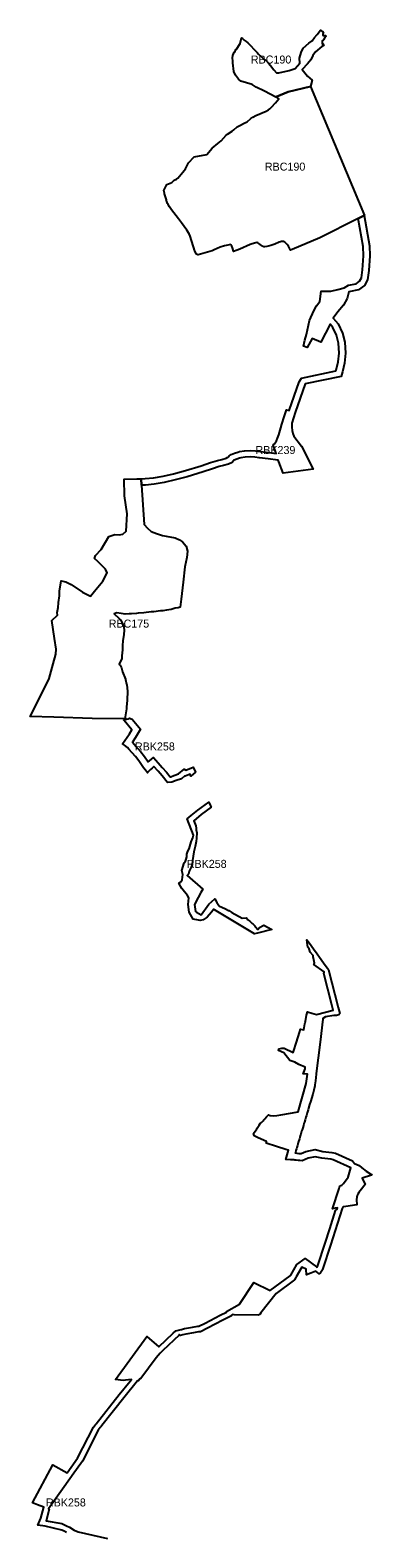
# Model space of a CAD drawing. Extents: x -559776 to -467147, y -1204122 to -1132159.
# Drawn here: x -525080 to -522945, y -1154789 to -1145407 of the extents above; entities that cross this region are included whole.
import ezdxf

# ---------------------------------------------------------------- set-up
doc = ezdxf.new("R2010")
doc.units = 0
doc.layers.add('regionalni_biocentrum_biokoridor', color=7, linetype='Continuous')

msp = doc.modelspace()

# ---------------------------------------------------------------- linework, layer by layer
at = {"layer": 'regionalni_biocentrum_biokoridor'}
for points in [[(-523328.59, -1145759.88), (-523468.67, -1145793.27), (-523542.77, -1145824.46), (-523545.77, -1145825.76), (-523615.41, -1145789.03), (-523667.45, -1145764.48), (-523693.27, -1145747.46), (-523763.57, -1145725.75), (-523777.48, -1145714.77), (-523796.61, -1145689.31), (-523807.7, -1145667.19), (-523813.88, -1145612.28), (-523814.22, -1145601.9), (-523815.48, -1145581.37), (-523813.04, -1145566.01), (-523804.95, -1145544.98), (-523801.67, -1145545.79), (-523794.39, -1145528.05), (-523790.57, -1145526.9), (-523768.76, -1145491.91), (-523759.9, -1145456.56), (-523754.01, -1145461.15), (-523742.67, -1145469.98), (-523731.15, -1145478.96), (-523720.44, -1145487.29), (-523713.2, -1145492.93), (-523709.93, -1145496.71), (-523701.08, -1145506.91), (-523683.05, -1145527.68), (-523672.48, -1145537.49), (-523666.5, -1145543.03), (-523662.57, -1145547.35), (-523653.56, -1145557.25), (-523643.62, -1145568.17), (-523643.15, -1145568.68), (-523632.99, -1145577.14), (-523621.63, -1145586.6), (-523611.12, -1145595.35), (-523600.24, -1145604.4), (-523598.48, -1145605.86), (-523590.58, -1145614.97), (-523579.19, -1145628.08), (-523558.38, -1145656.57), (-523540.6, -1145673.73), (-523527.41, -1145673.73), (-523461.42, -1145660.6), (-523424.36, -1145648.48), (-523395.43, -1145614.65), (-523398.27, -1145583.54), (-523387.82, -1145547.98), (-523375.43, -1145520.7), (-523338.07, -1145488.38), (-523317.77, -1145474.54), (-523304.56, -1145454.75), (-523287.31, -1145435.76), (-523267.06, -1145407.28), (-523256.85, -1145416.46), (-523251.78, -1145417.17), (-523247.21, -1145423.64), (-523252.49, -1145431.72), (-523251.98, -1145438.38), (-523247.51, -1145441.92), (-523235.53, -1145441.41), (-523231.47, -1145445.45), (-523239.59, -1145454.04), (-523247.41, -1145467.68), (-523256.65, -1145474.75), (-523256.35, -1145485.86), (-523254.82, -1145493.43), (-523248.73, -1145493.43), (-523245.69, -1145500.61), (-523246.7, -1145503.84), (-523258.38, -1145509.7), (-523298.48, -1145542.63), (-523314.72, -1145567.17), (-523326.29, -1145592.73), (-523347.82, -1145618.18), (-523380.71, -1145653.54), (-523346.6, -1145696.46), (-523317.28, -1145721.27)], [(-522992.95, -1146566.65), (-523030.28, -1146585.27), (-523269.51, -1146704.64), (-523442.49, -1146778.16), (-523452.8, -1146782.54), (-523466.08, -1146758.05), (-523474.04, -1146747.08), (-523488.03, -1146733.36), (-523497.91, -1146728.14), (-523504.09, -1146727.73), (-523513, -1146728.42), (-523515.75, -1146730.06), (-523523.84, -1146732.12), (-523551.69, -1146744.33), (-523576.39, -1146753.66), (-523601.63, -1146760.39), (-523612.88, -1146761.62), (-523619.47, -1146760.93), (-523630.44, -1146756.96), (-523635.52, -1146753.8), (-523650.75, -1146741.04), (-523657.34, -1146737.2), (-523664.74, -1146735.42), (-523670.78, -1146736.1), (-523693.56, -1146742.41), (-523704.53, -1146746.39), (-523769.84, -1146775.2), (-523786.28, -1146783.25), (-523809.62, -1146790.84), (-523809.97, -1146789.34), (-523815.13, -1146767.36), (-523819.69, -1146756.52), (-523825.77, -1146748.54), (-523829.13, -1146746.5), (-523845.3, -1146751.21), (-523865.35, -1146755.53), (-523892.08, -1146764.3), (-523929.45, -1146780.09), (-523942.48, -1146785.88), (-523972.89, -1146794.24), (-524031.16, -1146811.22), (-524032.66, -1146810.55), (-524041.24, -1146806.75), (-524048.27, -1146792.49), (-524055.49, -1146775.19), (-524056.17, -1146774.65), (-524061.93, -1146755.04), (-524080.73, -1146695.49), (-524087.18, -1146679.85), (-524101.31, -1146657.62), (-524135.06, -1146610.7), (-524153.53, -1146586.43), (-524168.26, -1146567.07), (-524197.76, -1146529.34), (-524209.69, -1146512.33), (-524218.2, -1146497.93), (-524222.32, -1146489.83), (-524226.57, -1146478.44), (-524229.39, -1146469.62), (-524227.27, -1146468.88), (-524240.45, -1146431.11), (-524241.49, -1146425.98), (-524244.67, -1146410.3), (-524225.11, -1146371.91), (-524195.5, -1146360.39), (-524179.33, -1146345.85), (-524165.85, -1146339.54), (-524156.42, -1146332.59), (-524126.78, -1146295.94), (-524110.34, -1146274.91), (-524090.06, -1146236.29), (-524055.32, -1146200.17), (-523976.43, -1146183.94), (-523942.62, -1146145.31), (-523908.09, -1146116.91), (-523887.2, -1146098.39), (-523854.77, -1146064.28), (-523847.53, -1146058.02), (-523817.45, -1146038.39), (-523807.43, -1146030.73), (-523786.83, -1146012.91), (-523774.29, -1146004.98), (-523738.93, -1145987.85), (-523725.01, -1145979.64), (-523701.62, -1145960.7), (-523688.53, -1145951.65), (-523669.32, -1145941.91), (-523605.28, -1145913.78), (-523590.1, -1145905.01), (-523581.89, -1145899.03), (-523571.59, -1145889.84), (-523546.8, -1145862.69), (-523526.82, -1145837.59), (-523525.63, -1145836.09), (-523542.77, -1145824.46), (-523468.67, -1145793.27), (-523328.59, -1145759.88), (-522991.63, -1146565.99)], [(-524384.36, -1148249.93), (-524387.2, -1148209.97), (-524360.86, -1148209.51), (-524310.26, -1148203.96), (-524249.87, -1148193.85), (-524184.46, -1148178.87), (-524109.46, -1148159.43), (-524010.79, -1148128.75), (-523953.91, -1148109.23), (-523910.07, -1148096), (-523881.6, -1148089.3), (-523855.21, -1148081.54), (-523844.16, -1148076.32), (-523843.28, -1148075.03), (-523837.47, -1148066.48), (-523823.87, -1148058.7), (-523803.1, -1148050.06), (-523783.55, -1148043.69), (-523771.2, -1148040.84), (-523740.54, -1148035.82), (-523704.99, -1148033.9), (-523673, -1148035.53), (-523642.94, -1148039.71), (-523641.55, -1148039.9), (-523588.54, -1148046.6), (-523588.34, -1148046.62), (-523586.84, -1148046.83), (-523544, -1148052.69), (-523562.36, -1147997.98), (-523553.74, -1147992.07), (-523541.36, -1147973.6), (-523534.7, -1147957.22), (-523527.12, -1147935.5), (-523513.12, -1147891.4), (-523506.7, -1147869.02), (-523492.7, -1147824.16), (-523478.7, -1147779.3), (-523462.51, -1147784.13), (-523400.32, -1147604.66), (-523384.75, -1147581.52), (-523169.63, -1147536.82), (-523168.02, -1147531.27), (-523155.93, -1147480.28), (-523149.35, -1147425.09), (-523153.27, -1147362.43), (-523166.15, -1147313.53), (-523189.1, -1147265.14), (-523206.66, -1147245.13), (-523265.17, -1147356.89), (-523319.05, -1147334.98), (-523348.92, -1147390.4), (-523373.08, -1147381.76), (-523364.97, -1147343.97), (-523352.7, -1147309.95), (-523334.45, -1147221.4), (-523307.51, -1147160.71), (-523291.18, -1147129.37), (-523269.94, -1147103.66), (-523262.99, -1147037.75), (-523202.43, -1147037.39), (-523158.09, -1147027.7), (-523119.3, -1147016.63), (-523091.75, -1147000.98), (-523044.3, -1146992.34), (-523022.55, -1146976.82), (-523011.03, -1146954.93), (-523004.31, -1146905.7), (-522997.18, -1146817.87), (-522999.43, -1146759.75), (-523030.28, -1146585.27), (-522992.95, -1146566.65), (-522959.56, -1146755.48), (-522957.11, -1146818.71), (-522964.53, -1146910.03), (-522972.35, -1146967.32), (-522991.59, -1147003.87), (-523028.03, -1147029.86), (-523089.24, -1147042.19), (-523089.18, -1147043.08), (-523098.8, -1147084.61), (-523122.9, -1147125.18), (-523157.66, -1147167.66), (-523186.51, -1147207.46), (-523155.35, -1147242.95), (-523128.42, -1147299.75), (-523113.59, -1147356.03), (-523109.2, -1147426.22), (-523116.48, -1147487.29), (-523129.33, -1147541.48), (-523137.93, -1147571.09), (-523362.52, -1147617.76), (-523424.14, -1147795.57), (-523446.06, -1147862.43), (-523445.99, -1147888.99), (-523443.71, -1147908.35), (-523439.28, -1147927.72), (-523433.19, -1147944.04), (-523385.73, -1148005.81), (-523311.46, -1148149.56), (-523499.46, -1148174.39), (-523526.76, -1148104.05), (-523529.84, -1148094.88), (-523531.97, -1148094.71), (-523592.25, -1148086.46), (-523593.68, -1148086.27), (-523646.71, -1148079.57), (-523646.98, -1148079.53), (-523648.47, -1148079.33), (-523676.78, -1148075.39), (-523704.93, -1148073.96), (-523736.22, -1148075.65), (-523763.47, -1148080.11), (-523772.84, -1148082.27), (-523789.2, -1148087.6), (-523806.18, -1148094.67), (-523809.59, -1148096.61), (-523810.19, -1148097.51), (-523817.2, -1148107.83), (-523840.95, -1148119.04), (-523871.37, -1148127.98), (-523899.7, -1148134.65), (-523941.63, -1148147.31), (-523998.35, -1148166.78), (-524098.5, -1148197.91), (-524174.97, -1148217.74), (-524242.1, -1148233.11), (-524304.78, -1148243.6), (-524358.32, -1148249.47)], [(-524384.36, -1148249.93), (-524366.88, -1148496.4), (-524346.87, -1148519.61), (-524323.9, -1148538.81), (-524291.41, -1148552.58), (-524252.45, -1148564.25), (-524230.46, -1148567.93), (-524173.78, -1148579.79), (-524146.15, -1148591.09), (-524127.26, -1148603.24), (-524105.83, -1148631.5), (-524097.64, -1148663.09), (-524101.88, -1148702.7), (-524113.16, -1148759.77), (-524123.88, -1148857.03), (-524136.61, -1148962.35), (-524142.42, -1149012.96), (-524156.26, -1149015.45), (-524172.23, -1149018.02), (-524173.23, -1149018.28), (-524187.43, -1149022.01), (-524199.6, -1149026), (-524227.53, -1149031.42), (-524251.68, -1149034.3), (-524264.85, -1149035.26), (-524307.55, -1149041.08), (-524322.14, -1149041.98), (-524322.95, -1149042.03), (-524369.71, -1149047.64), (-524405.64, -1149050.21), (-524415.52, -1149051.54), (-524446.68, -1149053.92), (-524449.17, -1149054.11), (-524450.55, -1149054.13), (-524461.34, -1149054.3), (-524486.62, -1149055.72), (-524511.07, -1149051.13), (-524538, -1149048.71), (-524553.96, -1149054.81), (-524525.62, -1149081.95), (-524514.99, -1149092.38), (-524506.29, -1149105.27), (-524500.34, -1149118.02), (-524494.39, -1149138.01), (-524492.47, -1149156.29), (-524493.75, -1149183.07), (-524500.55, -1149221.76), (-524503.95, -1149251.1), (-524502.87, -1149276.81), (-524503.22, -1149279.81), (-524506.08, -1149316.16), (-524508.06, -1149332.02), (-524514.86, -1149350.99), (-524523.07, -1149366.28), (-524519.57, -1149371.88), (-524517.4, -1149375.34), (-524510.04, -1149392.05), (-524502.12, -1149415.56), (-524484.33, -1149462.18), (-524483.76, -1149463.68), (-524476.96, -1149494.29), (-524476.67, -1149496.97), (-524472.28, -1149536.81), (-524473.77, -1149592.5), (-524477.6, -1149636.72), (-524478.9, -1149646.95), (-524485.25, -1149696.67), (-524483.35, -1149710.27), (-524691.47, -1149706.92), (-524932.69, -1149699.88), (-525080.41, -1149695.23), (-524988.64, -1149513.2), (-524960.53, -1149457.55), (-524935, -1149365.78), (-524918.32, -1149306.51), (-524917.56, -1149274.2), (-524926.95, -1149208.56), (-524944.02, -1149094.74), (-524909.04, -1149061.6), (-524910.3, -1149045.45), (-524904.13, -1149014.17), (-524903.47, -1148985.33), (-524903.27, -1148984.06), (-524896.51, -1148941.54), (-524897.16, -1148912.13), (-524885.39, -1148847.75), (-524857.29, -1148854.94), (-524823.94, -1148870.51), (-524752.05, -1148917.96), (-524703.06, -1148944.4), (-524676.85, -1148912.03), (-524626.72, -1148850.11), (-524598.78, -1148798.81), (-524608.77, -1148775.04), (-524614.84, -1148769.05), (-524657.84, -1148726.61), (-524678.33, -1148707.54), (-524671.48, -1148690.01), (-524636.19, -1148652.17), (-524588.31, -1148570.21), (-524551.77, -1148557.6), (-524524.04, -1148560.12), (-524500.22, -1148555.58), (-524479.72, -1148536.72), (-524473.36, -1148428.6), (-524491.08, -1148316.9), (-524492.33, -1148213.37), (-524413.53, -1148210.44), (-524387.2, -1148209.97)], [(-524364.97, -1149945.85), (-524342.06, -1149978.76), (-524336, -1149973.44), (-524334.02, -1149972.11), (-524309.74, -1149950.99), (-524280.2, -1149984.94), (-524254.67, -1150014.3), (-524228.9, -1150043.63), (-524205.34, -1150071.81), (-524202.06, -1150071.47), (-524181.76, -1150064.13), (-524152.65, -1150053.61), (-524118.61, -1150023.54), (-524108.08, -1150029.64), (-524061.87, -1150011.58), (-524047.91, -1150043.68), (-524075.86, -1150067.15), (-524080.52, -1150056.45), (-524111.03, -1150068.37), (-524114.34, -1150066.46), (-524134.48, -1150084.26), (-524166.91, -1150095.99), (-524194.19, -1150105.85), (-524219.25, -1150108.44), (-524223.51, -1150104.64), (-524255.48, -1150066.41), (-524281.02, -1150037.33), (-524306.61, -1150007.91), (-524308.5, -1150009.18), (-524318.5, -1150017.95), (-524328.49, -1150026.73), (-524342.8, -1150040.73), (-524347.38, -1150046.59), (-524359.18, -1150031.29), (-524370.98, -1150015.98), (-524401.24, -1149972.51), (-524422.58, -1149944.98), (-524442.52, -1149921.66), (-524462.46, -1149898.33), (-524472.06, -1149888.46), (-524490.35, -1149874.07), (-524502.75, -1149865.19), (-524459.38, -1149802.59), (-524444.91, -1149777.9), (-524493.33, -1149719.62), (-524495.53, -1149717.16), (-524494.71, -1149716.98), (-524493.03, -1149716.42), (-524467.23, -1149708.89), (-524459.72, -1149706.14), (-524441.52, -1149711.55), (-524390.14, -1149773.41), (-524421.42, -1149826.81), (-524441.32, -1149855.53), (-524429.2, -1149867.99), (-524408.31, -1149892.42), (-524387.68, -1149916.56)], [(-524039.95, -1150916.85), (-524010.61, -1150934.3), (-523964.34, -1150867.19), (-523927.03, -1150833.79), (-523913.6, -1150856.3), (-523908.92, -1150864.17), (-523901.66, -1150876.36), (-523900.33, -1150877.64), (-523897.63, -1150880.96), (-523882.7, -1150887.14), (-523860.13, -1150896.48), (-523841.01, -1150906.16), (-523837.85, -1150907.1), (-523820.03, -1150918.74), (-523756.3, -1150954.41), (-523728.56, -1150953.28), (-523719.83, -1150965.3), (-523707.49, -1150974.56), (-523692.26, -1150987.64), (-523687.06, -1150993.11), (-523676.9, -1151003.78), (-523671.29, -1151009.68), (-523656.71, -1151025.02), (-523647.43, -1151013.05), (-523624.35, -1151001.21), (-523623.67, -1151000.86), (-523620.52, -1150999.68), (-523569.52, -1151026.57), (-523660.12, -1151047.84), (-523677.59, -1151051.94), (-523928.99, -1150902.12), (-523932.16, -1150898.6), (-523947.53, -1150917.06), (-523973.28, -1150947.79), (-523999.04, -1150965.25), (-524018.42, -1150968.89), (-524028.09, -1150967.34), (-524061.84, -1150960.76), (-524086.77, -1150917.54), (-524093.24, -1150869.89), (-524088.69, -1150828.02), (-524097.36, -1150814.35), (-524133.06, -1150770.32), (-524148.78, -1150741.23), (-524150.56, -1150735.96), (-524141.27, -1150729.33), (-524130.16, -1150715.7), (-524125.44, -1150683.01), (-524131.35, -1150656.27), (-524118.03, -1150609.21), (-524109.91, -1150599.2), (-524104.88, -1150586.61), (-524101.03, -1150572.23), (-524100.14, -1150554.54), (-524095.4, -1150536.01), (-524087.42, -1150522.44), (-524074.11, -1150478.48), (-524063.61, -1150453.66), (-524059.46, -1150436.57), (-524099.54, -1150335.38), (-524073.03, -1150313.3), (-524033.16, -1150280.09), (-523963.56, -1150229.51), (-523952.79, -1150254.02), (-523948.96, -1150262.17), (-524011.65, -1150307.72), (-524057.69, -1150346.07), (-524044.68, -1150378.98), (-524042.03, -1150393.67), (-524042.85, -1150400.81), (-524042.94, -1150402.61), (-524043.02, -1150404.07), (-524039.65, -1150422.9), (-524041.4, -1150454.35), (-524042.03, -1150475.28), (-524049.64, -1150507.19), (-524057.48, -1150541.57), (-524064.71, -1150595.61), (-524067.83, -1150618.76), (-524074.29, -1150636.48), (-524085.64, -1150661.79), (-524091.01, -1150680.91), (-524098.25, -1150688.28), (-524001.97, -1150773.9), (-524012.87, -1150794.96), (-524029.58, -1150826.3), (-524052.24, -1150869.06), (-524047.18, -1150913.87)]]:
    msp.add_lwpolyline(points, close=True, dxfattribs=at)
msp.add_lwpolyline([(-524853.55, -1154791.44), (-524866.54, -1154784.46), (-524882.36, -1154777.7), (-524985.49, -1154753.86), (-525030.75, -1154747.09), (-525011.97, -1154703.85), (-524993.35, -1154635.12), (-525034.76, -1154620.16), (-525065.28, -1154606.98), (-524939.01, -1154369.98), (-524848.55, -1154420.24), (-524783.61, -1154329.06), (-524684.22, -1154133.8), (-524672.35, -1154118.61), (-524667.75, -1154113.16), (-524522.71, -1153930.16), (-524455.15, -1153847.84), (-524445.71, -1153836.35), (-524484.31, -1153841.34), (-524498.21, -1153842.8), (-524547.57, -1153836.95), (-524351.57, -1153567.24), (-524276.96, -1153632.44), (-524186.14, -1153546.55), (-524170.71, -1153531.96), (-524136.65, -1153524.07), (-524134.86, -1153523.66), (-524115.08, -1153519.07), (-524065.79, -1153510.22), (-524032.8, -1153503.53), (-524025.18, -1153503.29), (-523986.98, -1153484.15), (-523892.42, -1153435.18), (-523853.73, -1153415.35), (-523853.13, -1153412.04), (-523772.42, -1153367.17), (-523681.61, -1153231.41), (-523579.66, -1153281.75), (-523455.05, -1153189.56), (-523451.99, -1153185.62), (-523452.56, -1153185.32), (-523413.48, -1153118.77), (-523361.89, -1153079.91), (-523291.79, -1153132.94), (-523286.37, -1153135.45), (-523284.2, -1153131.38), (-523281.99, -1153125.06), (-523236.99, -1152986.13), (-523207.9, -1152895.46), (-523171.77, -1152780.17), (-523162.88, -1152772.81), (-523160.46, -1152763.88), (-523175.28, -1152765.79), (-523191.81, -1152771.14), (-523150.5, -1152644.2), (-523144.56, -1152625.94), (-523138.99, -1152624.86), (-523132.47, -1152623.6), (-523123.51, -1152611.93), (-523092.98, -1152572.22), (-523076.02, -1152515.52), (-523187.63, -1152464.45), (-523201.92, -1152461.18), (-523258.75, -1152455.17), (-523299.85, -1152445.15), (-523344.3, -1152454.08), (-523379.91, -1152470.8), (-523394.98, -1152469.24), (-523405.49, -1152468.29), (-523417.84, -1152467.11), (-523426.94, -1152465.7), (-523431.9, -1152465.04), (-523452.73, -1152464.25), (-523483.39, -1152462.03), (-523466.85, -1152404.16), (-523481.76, -1152399.52), (-523540.39, -1152381.23), (-523605.71, -1152360.89), (-523602.64, -1152355.45), (-523603.9, -1152350.16), (-523654.78, -1152326.69), (-523680.58, -1152314.86), (-523681.18, -1152313.09), (-523683.07, -1152306.28), (-523684.6, -1152299.77), (-523679.88, -1152292.94), (-523673.17, -1152283.35), (-523668.66, -1152276.54), (-523664.77, -1152271.34), (-523661.46, -1152266.25), (-523657.59, -1152261.06), (-523653.58, -1152255.05), (-523649.22, -1152248.86), (-523642.24, -1152238.22), (-523635.67, -1152231.24), (-523625.34, -1152219.98), (-523620.37, -1152214.75), (-523613.81, -1152207.52), (-523603.91, -1152196.95), (-523597.97, -1152190.35), (-523591.56, -1152183.74), (-523581.02, -1152188.38), (-523562.06, -1152190.04), (-523538.36, -1152187.39), (-523514.45, -1152183.96), (-523405.65, -1152163.83), (-523356.17, -1151987.39), (-523348.43, -1151929.85), (-523363.25, -1151927.05), (-523375.06, -1151927.67), (-523363.01, -1151895.74), (-523361.18, -1151885.75), (-523402.02, -1151868.08), (-523426.67, -1151855.03), (-523457.83, -1151844.22), (-523496.22, -1151796.19), (-523528.96, -1151782.6), (-523526.92, -1151770.57), (-523508.19, -1151766.7), (-523492.3, -1151766.9), (-523436.5, -1151793.82), (-523435.01, -1151788.48), (-523415.89, -1151728.85), (-523397.16, -1151670.04), (-523390.62, -1151649.27), (-523370.66, -1151652.13), (-523363.13, -1151614.93), (-523361.65, -1151606.42), (-523360.52, -1151600.76), (-523358.91, -1151600.49), (-523353.03, -1151561.25), (-523348.26, -1151540.63), (-523320.07, -1151548.12), (-523291.32, -1151556.31), (-523187.5, -1151529.81), (-523195.69, -1151497.04), (-523246.21, -1151301.05), (-523243.76, -1151290.73), (-523244.02, -1151290.95), (-523308.81, -1151243.56), (-523303.86, -1151235.89), (-523309.9, -1151205.34), (-523310.3, -1151203.26), (-523311.18, -1151198.67), (-523313.07, -1151188.9), (-523330.27, -1151167.55), (-523337.21, -1151146.32), (-523345.29, -1151135.57), (-523349.92, -1151106.79), (-523350.59, -1151090.49), (-523334.5, -1151111.52), (-523309.94, -1151146.29), (-523286.75, -1151178.52), (-523272.63, -1151198.43), (-523247.49, -1151233.88), (-523218.8, -1151273.94), (-523217.97, -1151274.93), (-523216.07, -1151277.76), (-523155.6, -1151513.69), (-523144.76, -1151549.53), (-523150.68, -1151558.66), (-523165.72, -1151562.88), (-523182.96, -1151562.55), (-523235.73, -1151572.17), (-523251.46, -1151581.67), (-523250.56, -1151581.5), (-523250.98, -1151585), (-523268.28, -1151729.81), (-523293.14, -1151924.53), (-523293.36, -1151928.98), (-523298.26, -1151970.24), (-523301.25, -1151996.57), (-523301.81, -1152003.36), (-523308.7, -1152029.82), (-523314.69, -1152055.26), (-523328.36, -1152101.78), (-523334, -1152119.07), (-523341, -1152141.56), (-523344.21, -1152152.46), (-523349.57, -1152170.4), (-523354.43, -1152187.05), (-523357.8, -1152197.84), (-523362.75, -1152215.16), (-523366.78, -1152228.82), (-523369.75, -1152238.29), (-523373.21, -1152250.5), (-523377.58, -1152264.35), (-523381.44, -1152276.93), (-523384.16, -1152285.66), (-523386.14, -1152293.09), (-523389.51, -1152305.11), (-523392.56, -1152314.42), (-523395.86, -1152324.39), (-523398.08, -1152332.46), (-523400.22, -1152339.21), (-523403.52, -1152350.18), (-523405.16, -1152356.92), (-523407.64, -1152365.67), (-523410.6, -1152375.71), (-523414.31, -1152387.81), (-523416.45, -1152395.08), (-523419.91, -1152407.27), (-523423.12, -1152417.8), (-523424.14, -1152421.02), (-523414.41, -1152423.39), (-523401.44, -1152424.63), (-523390.75, -1152425.59), (-523387.51, -1152425.93), (-523358.14, -1152412.13), (-523298.93, -1152400.25), (-523251.22, -1152411.87), (-523194.69, -1152417.85), (-523173.46, -1152422.71), (-523066.85, -1152471.5), (-523053.39, -1152487.16), (-523024.52, -1152500.07), (-523009.07, -1152514.63), (-522981.51, -1152534.93), (-522951.14, -1152553.13), (-522944.82, -1152556.92), (-522946.76, -1152559.91), (-523005.67, -1152579.44), (-522986.41, -1152618.73), (-523018.97, -1152658.51), (-523027.56, -1152669.32), (-523033.1, -1152678.47), (-523036.98, -1152687.06), (-523039.48, -1152698.15), (-523041.14, -1152712.85), (-523040.16, -1152746.01), (-523108.77, -1152756.34), (-523125.17, -1152758.89), (-523127.28, -1152759.22), (-523131.3, -1152768.08), (-523174.54, -1152906.04), (-523203.68, -1152996.86), (-523250.96, -1153142.86), (-523254.36, -1153150.28), (-523253.49, -1153150.67), (-523265.28, -1153170.73), (-523274.04, -1153176.96), (-523296.1, -1153160.49), (-523325.78, -1153172.52), (-523353.02, -1153183.57), (-523355.6, -1153148.02), (-523382.18, -1153134.59), (-523418.3, -1153196.1), (-523420.31, -1153200.45), (-523428.48, -1153213.43), (-523543.23, -1153299.71), (-523638.26, -1153420.35), (-523645.21, -1153431.33), (-523655.45, -1153435.35), (-523805.01, -1153433.52), (-523815.07, -1153430.92), (-523821.65, -1153434.58), (-523822.38, -1153438.61), (-523876.39, -1153466.29), (-523971.09, -1153515.34), (-524016.38, -1153538.02), (-524028.73, -1153538.42), (-524059.22, -1153544.6), (-524108.04, -1153553.37), (-524126.96, -1153557.75), (-524140.59, -1153560.91), (-524149.81, -1153556.56), (-524149.43, -1153560.01), (-524250.49, -1153655.57), (-524267.39, -1153671.56), (-524291.78, -1153701.68), (-524388.84, -1153829.95), (-524393.26, -1153832.93), (-524394.06, -1153832.85), (-524403.97, -1153844.22), (-524408.27, -1153845.88), (-524495.47, -1153952.14), (-524631.14, -1154123.32), (-524632.98, -1154123.79), (-524636.87, -1154130.51), (-524642.59, -1154137.38), (-524654.57, -1154152.7), (-524753.6, -1154347.25), (-524817.77, -1154437.34), (-524820.98, -1154441.85), (-524964.93, -1154645.39), (-524960.32, -1154647.06), (-524979.88, -1154719.24), (-524881.77, -1154736.5), (-524852.21, -1154749.94), (-524834.29, -1154758.9), (-524804.72, -1154778.61), (-524779.63, -1154788.46), (-524595.97, -1154830.57)], dxfattribs=at)

# ---------------------------------------------------------------- texts
for s, p in [('RBC190', (-523701.32, -1145616.52)), ('RBC190', (-523613.76, -1146285.55)), ('RBK239', (-523672.15, -1148055.84)), ('RBC175', (-524589.03, -1149140)), ('RBK258', (-524425.2, -1149907.29)), ('RBK258', (-524101.57, -1150640.73)), ('RBK258', (-524981.1, -1154629.69))]:
    msp.add_text(s, height=50, dxfattribs=at).set_placement(p)

doc.saveas('drawing.dxf')
